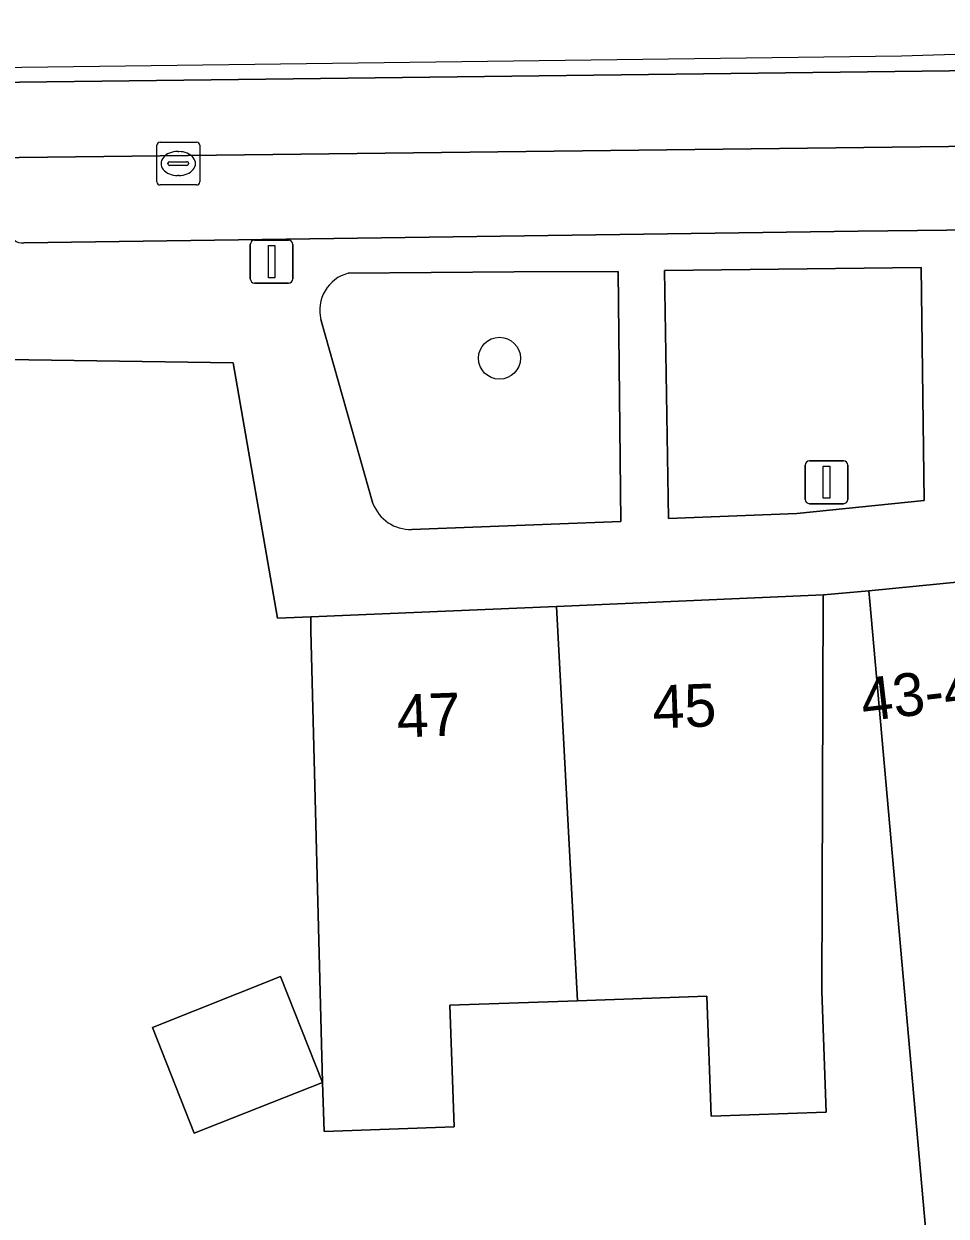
# Model space of a CAD drawing. Extents: x 159960 to 160866, y 382700 to 383354.
# Drawn here: x 160014.72 to 160036.23, y 383263.3 to 383291.12 of the extents above; entities that cross this region are included whole.
import ezdxf

# ---------------------------------------------------------------- set-up
doc = ezdxf.new("R2010")
doc.units = 0
for name, color, linetype in [('IMGEO_Boom', 7, 'Continuous'), ('IMGEO_Erf', 7, 'Continuous'), ('IMGEO_Groenvoorziening', 7, 'Continuous'), ('IMGEO_Kolk', 7, 'Continuous'), ('IMGEO_Lichtmast', 7, 'Continuous'), ('IMGEO_Pand', 7, 'Continuous'), ('IMGEO_Pand_nummerreeks', 7, 'Continuous'), ('IMGEO_Parkeervlak_open', 7, 'Continuous'), ('IMGEO_Rijbaan_lokaal_gesloten', 7, 'Continuous'), ('IMGEO_Rijbaan_lokaal_open', 7, 'Continuous'), ('IMGEO_Voetpad_open', 7, 'Continuous')]:
    doc.layers.add(name, color=color, linetype=linetype)

msp = doc.modelspace()

# ---------------------------------------------------------------- linework, layer by layer
at = {"layer": 'IMGEO_Boom'}
msp.add_circle((160025.815, 383283.322), 0.489, dxfattribs=at)
at = {"layer": 'IMGEO_Erf'}
msp.add_lwpolyline([(160035.818, 383262.243), (160034.451, 383277.646), (160034.427, 383277.894), (160033.368, 383277.799), (160033.361, 383277.75), (160033.333, 383268.553), (160033.433, 383265.73), (160030.748, 383265.634), (160030.648, 383268.439), (160027.633, 383268.331), (160024.66, 383268.225), (160024.761, 383265.387), (160021.726, 383265.279), (160021.685, 383266.426), (160021.414, 383276.968), (160021.414, 383277.287), (160020.642, 383277.254), (160019.606, 383283.216), (160000, 383283.499)], dxfattribs=at)
msp.add_lwpolyline([(160021.685, 383266.426), (160018.699, 383265.242), (160017.72, 383267.709), (160020.707, 383268.893)], close=True, dxfattribs=at)
at = {"layer": 'IMGEO_Groenvoorziening'}
msp.add_lwpolyline([(160029.661, 383285.371), (160029.758, 383279.58), (160032.747, 383279.699), (160035.715, 383280), (160035.648, 383285.441)], close=True, dxfattribs=at)
for points in [[(160026.155, 383285.341), (160022.289, 383285.305)], [(160023.769, 383279.326), (160028.641, 383279.513), (160028.586, 383285.343), (160026.155, 383285.341)], [(160021.651, 383284.225), (160022.865, 383279.93)]]:
    msp.add_lwpolyline(points, dxfattribs=at)
for centre, radius, start, end in [((160022.509, 383284.446), 0.886, 104.395, 194.4609), ((160023.743, 383280.266), 0.94, 200.9319, 271.571)]:
    msp.add_arc(centre, radius, start, end, dxfattribs=at)
at = {"layer": 'IMGEO_Kolk'}
for p, q in [((160017.824, 383287.438), (160017.824, 383288.29)), ((160017.899, 383288.364), (160018.751, 383288.364)), ((160018.825, 383288.29), (160018.825, 383287.438)), ((160018.126, 383287.907), (160018.524, 383287.907)), ((160018.312, 383288.144), (160018.337, 383288.144)), ((160018.083, 383287.858), (160018.083, 383287.87)), ((160018.521, 383287.821), (160018.123, 383287.821)), ((160018.567, 383287.87), (160018.567, 383287.858)), ((160018.751, 383287.364), (160017.899, 383287.364)), ((160018.335, 383287.584), (160018.31, 383287.584))]:
    msp.add_line(p, q, dxfattribs=at)
for points in [[(160017.824, 383287.438), (160017.824, 383288.29)], [(160017.899, 383288.364), (160018.751, 383288.364)], [(160018.825, 383288.29), (160018.825, 383287.438)], [(160018.751, 383287.364), (160017.899, 383287.364)]]:
    msp.add_lwpolyline(points, dxfattribs=at)
for centre, radius, start, end in [((160017.901, 383288.288), 0.0765, 91.552, 178.448), ((160017.901, 383288.288), 0.0765, 91.552, 178.448), ((160018.749, 383288.288), 0.0765, 1.552, 88.448), ((160018.749, 383288.288), 0.0765, 1.552, 88.448), ((160018.123, 383287.867), 0.0403, 85.8775, 175.7526), ((160018.528, 383287.869), 0.0386, 1.7309, 96.639), ((160018.12, 383287.857), 0.0366, 178.938, 274.7102), ((160018.524, 383287.864), 0.043, 264.8664, 352.4533), ((160017.901, 383287.44), 0.0765, 181.552, 268.448), ((160017.901, 383287.44), 0.0765, 181.552, 268.448), ((160018.749, 383287.44), 0.0765, 271.552, 358.448), ((160018.749, 383287.44), 0.0765, 271.552, 358.448)]:
    msp.add_arc(centre, radius, start, end, dxfattribs=at)
for centre, major_axis, ratio, start_param, end_param in [((160018.311, 383287.864), (-0.387, 0.002), 0.722429, 4.712389, 7.853982), ((160018.336, 383287.864), (-0.39, 0.002), 0.717154, 1.570796, 4.712389)]:
    msp.add_ellipse(centre, major_axis=major_axis, ratio=ratio, start_param=start_param, end_param=end_param, dxfattribs=at)
at = {"layer": 'IMGEO_Lichtmast'}
for p, q in [((160020.005, 383285.176), (160020.005, 383285.976)), ((160020.005, 383285.976), (160020.005, 383285.176)), ((160020.105, 383286.076), (160020.895, 383286.076)), ((160020.895, 383286.076), (160020.105, 383286.076)), ((160020.995, 383285.976), (160020.995, 383285.176)), ((160020.995, 383285.176), (160020.995, 383285.976)), ((160020.895, 383285.076), (160020.105, 383285.076)), ((160020.105, 383285.076), (160020.895, 383285.076)), ((160033.046, 383280.928), (160033.836, 383280.928)), ((160033.836, 383280.928), (160033.046, 383280.928)), ((160032.946, 383280.028), (160032.946, 383280.828)), ((160032.946, 383280.828), (160032.946, 383280.028)), ((160033.936, 383280.828), (160033.936, 383280.028)), ((160033.936, 383280.028), (160033.936, 383280.828)), ((160033.836, 383279.928), (160033.046, 383279.928)), ((160033.046, 383279.928), (160033.836, 383279.928))]:
    msp.add_line(p, q, dxfattribs=at)
for points in [[(160020.425, 383285.951), (160020.575, 383285.951), (160020.575, 383285.201), (160020.425, 383285.201), (160020.425, 383285.951)], [(160033.366, 383280.803), (160033.516, 383280.803), (160033.516, 383280.053), (160033.366, 383280.053), (160033.366, 383280.803)]]:
    msp.add_lwpolyline(points, dxfattribs=at)
for centre, start, end in [((160020.105, 383285.976), 90, 180), ((160020.105, 383285.976), 90, 180), ((160020.895, 383285.976), 0, 90), ((160020.895, 383285.976), 360, 90), ((160020.105, 383285.176), 180, 270), ((160020.105, 383285.176), 180, 270), ((160020.895, 383285.176), 270, 0), ((160020.895, 383285.176), 270, 0), ((160033.046, 383280.828), 90, 180), ((160033.046, 383280.828), 90, 180), ((160033.836, 383280.828), 0, 90), ((160033.836, 383280.828), 360, 90), ((160033.046, 383280.028), 180, 270), ((160033.046, 383280.028), 180, 270), ((160033.836, 383280.028), 270, 0), ((160033.836, 383280.028), 270, 0)]:
    msp.add_arc(centre, 0.1, start, end, dxfattribs=at)
at = {"layer": 'IMGEO_Pand'}
for points in [[(160040.495, 383278.49), (160034.427, 383277.894), (160034.451, 383277.646), (160035.818, 383262.243), (160038.03, 383254.521), (160038.602, 383251.781), (160043.484, 383252.16), (160042.76, 383261.226), (160042.73, 383261.604), (160041.745, 383263.795)], [(160033.361, 383277.75), (160033.368, 383277.799), (160027.145, 383277.532), (160027.633, 383268.331), (160030.648, 383268.439), (160030.748, 383265.634), (160033.433, 383265.73), (160033.333, 383268.553)], [(160027.145, 383277.532), (160021.414, 383277.287), (160021.414, 383276.968), (160021.685, 383266.426), (160021.726, 383265.279), (160024.761, 383265.387), (160024.66, 383268.225), (160027.633, 383268.331)], [(160017.72, 383267.709), (160018.699, 383265.242), (160021.685, 383266.426), (160020.707, 383268.893)]]:
    msp.add_lwpolyline(points, close=True, dxfattribs=at)
at = {"layer": 'IMGEO_Parkeervlak_open'}
for points in [[(160059.777, 383288.576), (160055.475, 383288.504), (160036.94, 383288.267), (160013.952, 383287.999)], [(160014.724, 383286.017), (160034.176, 383286.285), (160059.032, 383286.566)]]:
    msp.add_lwpolyline(points, dxfattribs=at)
msp.add_arc((160014.675, 383286.27), 0.258, 172.0073, 280.8907, dxfattribs=at)
at = {"layer": 'IMGEO_Rijbaan_lokaal_gesloten'}
for points in [[(160059.258, 383290.327), (160036.947, 383290.034), (160008.881, 383289.691), (159997.814, 383289.529)], [(159998.744, 383287.782), (160007.95, 383287.922), (160013.952, 383287.999), (160036.94, 383288.267), (160055.475, 383288.504), (160059.777, 383288.576), (160061.559, 383288.528), (160061.542, 383290.365), (160059.258, 383290.327)]]:
    msp.add_lwpolyline(points, dxfattribs=at)
at = {"layer": 'IMGEO_Rijbaan_lokaal_open'}
msp.add_lwpolyline([(160059.246, 383291.123), (160050.172, 383290.838), (160035.187, 383290.367), (159997.778, 383289.885), (159997.814, 383289.529), (160008.881, 383289.691), (160036.947, 383290.034), (160059.258, 383290.327)], close=True, dxfattribs=at)
at = {"layer": 'IMGEO_Voetpad_open'}
for points in [[(160059.032, 383286.566), (160034.176, 383286.285), (160014.724, 383286.017)], [(160022.289, 383285.305), (160026.155, 383285.341), (160028.586, 383285.343), (160028.641, 383279.513), (160023.769, 383279.326)], [(160022.865, 383279.93), (160021.651, 383284.225)], [(159996.758, 383283.546), (160000, 383283.499), (160019.606, 383283.216), (160020.642, 383277.254), (160021.414, 383277.287), (160027.145, 383277.532), (160033.368, 383277.799), (160034.427, 383277.894), (160040.495, 383278.49), (160046.395, 383279.069), (160047.368, 383279.124), (160052.517, 383279.609), (160053.242, 383279.684), (160061.342, 383280.521), (160061.373, 383280.559), (160062.543, 383279.597), (160066.298, 383280.383), (160065.906, 383283.389)]]:
    msp.add_lwpolyline(points, dxfattribs=at)
msp.add_lwpolyline([(160029.661, 383285.371), (160035.648, 383285.441), (160035.715, 383280), (160032.747, 383279.699), (160029.758, 383279.58)], close=True, dxfattribs=at)
for centre, radius, start, end in [((160014.675, 383286.27), 0.258, 172.0073, 280.8907), ((160022.509, 383284.446), 0.886, 104.395, 194.4609), ((160023.743, 383280.266), 0.94, 200.9319, 271.571)]:
    msp.add_arc(centre, radius, start, end, dxfattribs=at)

# ---------------------------------------------------------------- texts
at = {"layer": 'IMGEO_Pand_nummerreeks'}
for s, rotation, p in [('43-43B', 6.7666, (160034.302, 383274.846)), ('45', 2.0455, (160029.399, 383274.683)), ('47', 2.0455, (160023.435, 383274.47))]:
    msp.add_text(s, height=1, rotation=rotation, dxfattribs=at).set_placement(p)

doc.saveas('drawing.dxf')
